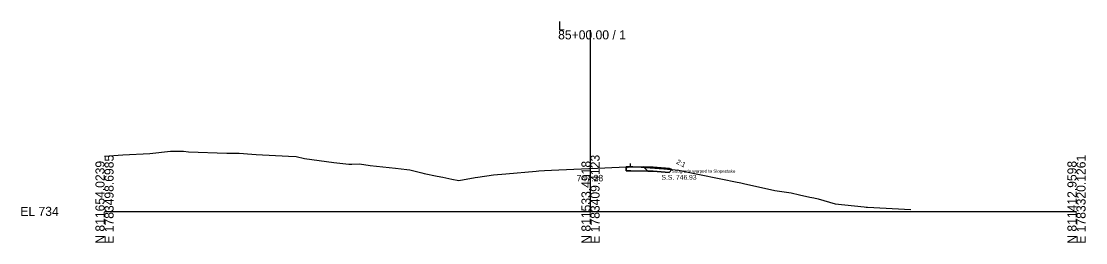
# Model space of a CAD drawing. Extents: x -26 to 7903, y -10 to 9573.
# Drawn here: x 4974.3 to 5302.8, y 5990.3 to 6058.8 of the extents above; entities that cross this region are included whole.
import ezdxf

# ---------------------------------------------------------------- set-up
doc = ezdxf.new("R2010")
doc.units = 0
for name, color, linetype in [('Exist Cross Section Cell', 7, 'Continuous'), ('Exist XS Center Line Elevation Label', 7, 'Continuous'), ('Exist XS Ground Line', 7, 'Continuous'), ('Prop XS Dump Level', 7, 'Continuous'), ('Prop XS Earthwork Shape', 7, 'Continuous'), ('Prop XS EOT Tick Mark', 7, 'Continuous'), ('Prop XS Finish Grade', 7, 'Continuous'), ('Prop XS Finish Grade Paved Shoulder', 7, 'Continuous'), ('Prop XS Finish Grade Pavement', 7, 'Continuous'), ('Prop XS Pvmt Edge Slope', 7, 'Continuous'), ('Prop XS Side Slope Text', 7, 'Continuous'), ('Prop XS SS Elevation Text', 7, 'Continuous'), ('Prop XS Subgrade Earthwork', 7, 'Continuous'), ('Scratch_Level_3', 7, 'Continuous'), ('Scratch_Level_6', 7, 'Continuous')]:
    doc.layers.add(name, color=color, linetype=linetype)

msp = doc.modelspace()

# ---------------------------------------------------------------- linework, layer by layer
at = {"layer": 'Exist Cross Section Cell'}
for p, q in [((5150, 6000), (5150, 6055.95)), ((5000, 6000), (5150, 6000)), ((5150, 6000), (5300, 6000))]:
    msp.add_line(p, q, dxfattribs=at)
at = {"layer": 'Exist XS Ground Line'}
for p, q in [((5000, 6017.09), (5005.64, 6017.49)), ((5005.64, 6017.49), (5013.95, 6017.91)), ((5013.95, 6017.91), (5020.36, 6018.62)), ((5020.36, 6018.62), (5024.37, 6018.65)), ((5024.37, 6018.65), (5025.9, 6018.43)), ((5025.9, 6018.43), (5037.75, 6018.03)), ((5037.75, 6018.03), (5041.52, 6018)), ((5041.52, 6018), (5045.44, 6017.67)), ((5045.44, 6017.67), (5046.81, 6017.62)), ((5046.81, 6017.62), (5056.8, 6017.09)), ((5056.8, 6017.09), (5059.18, 6016.98)), ((5059.18, 6016.98), (5061.73, 6016.35)), ((5061.73, 6016.35), (5070.77, 6015.09)), ((5070.77, 6015.09), (5075.42, 6014.64)), ((5075.42, 6014.64), (5076.31, 6014.63)), ((5076.31, 6014.63), (5078.73, 6014.74)), ((5078.73, 6014.74), (5081.94, 6014.2)), ((5081.94, 6014.2), (5089.85, 6013.4)), ((5089.85, 6013.4), (5093.28, 6012.89)), ((5093.28, 6012.89), (5094.26, 6012.84)), ((5094.26, 6012.84), (5097.92, 6011.87)), ((5123.85, 6011.56), (5133.2, 6012.45)), ((5133.2, 6012.45), (5134.05, 6012.54)), ((5134.05, 6012.54), (5135.78, 6012.63)), ((5135.78, 6012.63), (5137.94, 6012.74)), ((5137.94, 6012.74), (5149.5, 6013.26)), ((5149.5, 6013.26), (5150, 6013.28)), ((5150, 6013.28), (5160.96, 6013.74)), ((5160.96, 6013.74), (5163.02, 6013.72)), ((5163.02, 6013.72), (5165.67, 6013.68)), ((5165.67, 6013.68), (5171.18, 6013.25)), ((5171.18, 6013.25), (5172.59, 6013.14)), ((5172.59, 6013.14), (5177.24, 6012.75)), ((5177.24, 6012.75), (5177.67, 6012.68)), ((5177.67, 6012.68), (5182.59, 6011.65)), ((5097.92, 6011.87), (5098.66, 6011.66)), ((5098.66, 6011.66), (5102.71, 6010.91)), ((5102.71, 6010.91), (5104.44, 6010.53)), ((5104.44, 6010.53), (5107.21, 6009.94)), ((5107.21, 6009.94), (5109.32, 6009.55)), ((5109.32, 6009.55), (5114.36, 6010.42)), ((5114.36, 6010.42), (5115.23, 6010.55)), ((5115.23, 6010.55), (5120.09, 6011.29)), ((5120.09, 6011.29), (5123.85, 6011.56)), ((5182.59, 6011.65), (5190.78, 6009.96)), ((5190.78, 6009.96), (5194.74, 6009.12)), ((5194.74, 6009.12), (5196.42, 6008.77)), ((5196.42, 6008.77), (5197.23, 6008.58)), ((5197.23, 6008.58), (5206.85, 6006.49)), ((5206.85, 6006.49), (5211.94, 6005.68)), ((5211.94, 6005.68), (5214.5, 6005.13)), ((5214.5, 6005.13), (5217.65, 6004.4)), ((5217.65, 6004.4), (5218.93, 6004.15)), ((5218.93, 6004.15), (5220.29, 6003.85)), ((5220.29, 6003.85), (5225.52, 6002.33)), ((5225.52, 6002.33), (5234.41, 6001.4)), ((5234.41, 6001.4), (5235.06, 6001.29)), ((5235.06, 6001.29), (5235.54, 6001.28)), ((5235.54, 6001.28), (5248.86, 6000.56))]:
    msp.add_line(p, q, dxfattribs=at)
at = {"layer": 'Prop XS Dump Level'}
msp.add_line((5160.95, 6013.72), (5162.38, 6013.77), dxfattribs=at)
at = {"layer": 'Prop XS Earthwork Shape'}
msp.add_lwpolyline([(5165.67, 6013.68), (5171.18, 6013.25), (5172.59, 6013.14), (5175.08, 6012.93), (5174.28, 6012.03), (5169.32, 6012.43), (5167.66, 6012.46), (5162.4, 6012.55), (5160.96, 6012.49), (5160.96, 6013.74), (5163.02, 6013.72)], close=True, dxfattribs=at)
at = {"layer": 'Prop XS EOT Tick Mark'}
msp.add_line((5162.38, 6013.8), (5162.38, 6014.8), dxfattribs=at)
at = {"layer": 'Prop XS Finish Grade'}
for p, q in [((5166.38, 6013.73), (5169.38, 6013.68)), ((5169.38, 6013.68), (5174.38, 6013.28)), ((5174.38, 6013.28), (5175.08, 6012.93))]:
    msp.add_line(p, q, dxfattribs=at)
at = {"layer": 'Prop XS Finish Grade Paved Shoulder'}
msp.add_line((5162.38, 6013.8), (5166.38, 6013.73), dxfattribs=at)
at = {"layer": 'Prop XS Finish Grade Pavement'}
msp.add_line((5160.96, 6013.74), (5162.38, 6013.8), dxfattribs=at)
at = {"layer": 'Prop XS Pvmt Edge Slope'}
msp.add_line((5166.38, 6013.73), (5167.66, 6012.46), dxfattribs=at)
at = {"layer": 'Prop XS Subgrade Earthwork'}
for p, q in [((5160.96, 6012.49), (5160.96, 6013.74)), ((5160.96, 6012.49), (5162.4, 6012.55)), ((5162.4, 6012.55), (5167.66, 6012.46)), ((5167.66, 6012.46), (5169.32, 6012.43)), ((5169.32, 6012.43), (5174.28, 6012.03)), ((5174.28, 6012.03), (5175.08, 6012.93))]:
    msp.add_line(p, q, dxfattribs=at)
at = {"layer": 'Scratch_Level_3'}
for p, q in [((5169.38, 6013.68), (5166.38, 6013.73)), ((5166.38, 6013.73), (5167.66, 6012.46)), ((5167.66, 6012.46), (5169.32, 6012.43)), ((5169.32, 6012.43), (5174.28, 6012.03)), ((5174.38, 6013.28), (5169.38, 6013.68)), ((5174.28, 6012.03), (5175.08, 6012.93)), ((5175.08, 6012.93), (5174.38, 6013.28))]:
    msp.add_line(p, q, dxfattribs=at)
at = {"layer": 'Scratch_Level_6'}
msp.add_lwpolyline([(5167.66, 6012.46), (5169.32, 6012.43), (5174.28, 6012.03), (5175.08, 6012.93), (5172.59, 6013.14), (5171.18, 6013.25), (5165.67, 6013.68), (5163.02, 6013.72), (5160.96, 6013.74), (5160.96, 6012.49), (5162.4, 6012.55)], close=True, dxfattribs=at)

# ---------------------------------------------------------------- texts
at = {"layer": 'Exist Cross Section Cell'}
for s, p in [('L', (5140, 6055.95)), ('85+00.00 / 1', (5140, 6053.15)), ('EL 734', (4974, 5998.6))]:
    msp.add_text(s, height=2.8, dxfattribs=at).set_placement(p)
for s, p in [('E 1783498.6985', (5002.8, 5990)), ('N 811533.4918', (5150, 5990)), ('E 1783409.4123', (5152.8, 5990)), ('N 811412.9598', (5300, 5990)), ('E 1783320.1261', (5302.8, 5990)), ('N 811654.0239', (5000, 5990))]:
    msp.add_text(s, height=2.8, rotation=90, dxfattribs=at).set_placement(p)
at = {"layer": 'Exist XS Center Line Elevation Label'}
msp.add_text('747.28', height=2, dxfattribs=at).set_placement((5145.73, 6009.28))
at = {"layer": 'Prop XS Dump Level'}
for s, height, p in [('Eop', 0.3, (5160.96, 6013.44)), ('Case4', 0.04, (5174.38, 6013.24)), ('Subgrade warped to Slopestake', 1, (5175.08, 6011.93))]:
    msp.add_text(s, height=height, dxfattribs=at).set_placement(p)
at = {"layer": 'Prop XS Side Slope Text'}
msp.add_text('2:1', height=1.5, rotation=333.4349, dxfattribs=at).set_placement((5176.32, 6014.83))
at = {"layer": 'Prop XS SS Elevation Text'}
msp.add_text('S.S. 746.93', height=1.5, dxfattribs=at).set_placement((5171.9, 6009.77))

doc.saveas('drawing.dxf')
